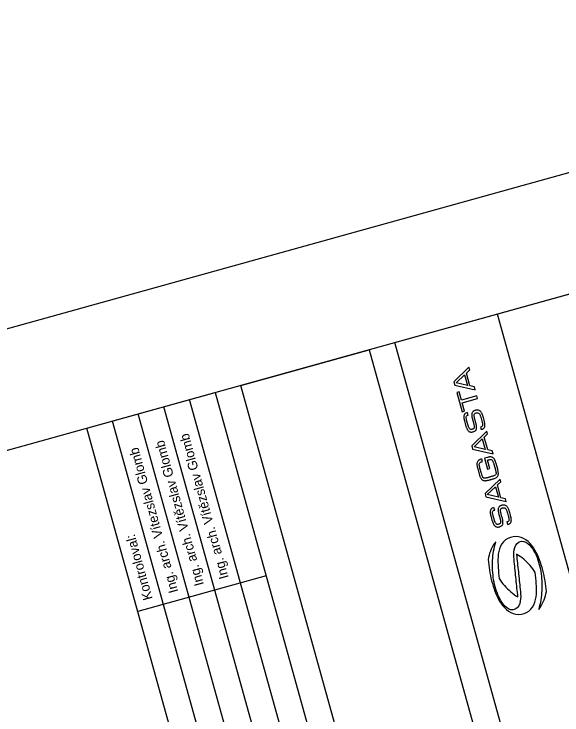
# Model space of a CAD drawing. Extents: x -821172 to -820632, y -1070921 to -1069931.
# Drawn here: x -820991 to -820939.6, y -1069996.3 to -1069930.6 of the extents above; entities that cross this region are included whole.
import ezdxf

# ---------------------------------------------------------------- set-up
doc = ezdxf.new("R2010")
doc.units = 0
doc.layers.add('Popisove_pole', color=7, linetype='Continuous')
doc.layers.add('Ram', color=7, linetype='Continuous')

# ---------------------------------------------------------------- blocks, each defined once
blk = doc.blocks.new('sagasta-logo')
at = {"layer": 'Popisove_pole'}
for p, q in [((-4.235, 0.826), (-4.328, 0.783)), ((-4.267, 0.757), (-4.186, 0.794)), ((-4.14, 0.863), (-4.235, 0.826)), ((-4.186, 0.794), (-4.101, 0.825)), ((-4.043, 0.893), (-4.14, 0.863)), ((-4.101, 0.825), (-4.015, 0.85)), ((-3.943, 0.916), (-4.043, 0.893)), ((-4.015, 0.85), (-3.927, 0.869)), ((-3.843, 0.934), (-3.943, 0.916)), ((-3.927, 0.869), (-3.838, 0.884)), ((-3.742, 0.949), (-3.843, 0.934)), ((-3.838, 0.884), (-3.749, 0.895)), ((-3.749, 0.895), (-3.659, 0.903)), ((-3.641, 0.96), (-3.742, 0.949)), ((-3.659, 0.903), (-3.569, 0.907)), ((-3.539, 0.968), (-3.641, 0.96)), ((-3.569, 0.907), (-3.479, 0.908)), ((-3.437, 0.972), (-3.539, 0.968)), ((-3.479, 0.908), (-3.389, 0.906)), ((-3.335, 0.975), (-3.437, 0.972)), ((-3.389, 0.906), (-3.3, 0.901)), ((-3.233, 0.976), (-3.335, 0.975)), ((-3.3, 0.901), (-3.21, 0.892)), ((-3.131, 0.975), (-3.233, 0.976)), ((-3.21, 0.892), (-3.121, 0.881)), ((-3.03, 0.97), (-3.131, 0.975)), ((-3.121, 0.881), (-3.032, 0.867)), ((-3.032, 0.867), (-2.944, 0.85)), ((-2.928, 0.962), (-3.03, 0.97)), ((-2.944, 0.85), (-2.855, 0.832)), ((-2.827, 0.951), (-2.928, 0.962)), ((-2.855, 0.832), (-2.768, 0.81)), ((-2.726, 0.938), (-2.827, 0.951)), ((-2.768, 0.81), (-2.681, 0.787)), ((-2.625, 0.922), (-2.726, 0.938)), ((-2.524, 0.907), (-2.625, 0.922)), ((-2.423, 0.891), (-2.524, 0.907)), ((-2.35, 0.855), (-2.423, 0.891)), ((-2.28, 0.814), (-2.35, 0.855)), ((-2.211, 0.77), (-2.28, 0.814)), ((-4.572, 0.602), (-4.634, 0.521)), ((-4.497, 0.67), (-4.572, 0.602)), ((-4.415, 0.731), (-4.497, 0.67)), ((-4.493, 0.493), (-4.465, 0.578)), ((-4.465, 0.578), (-4.412, 0.65)), ((-4.328, 0.783), (-4.415, 0.731)), ((-4.412, 0.65), (-4.343, 0.708)), ((-4.343, 0.708), (-4.267, 0.757)), ((-3.532, 0.564), (-3.606, 0.526)), ((-3.457, 0.599), (-3.532, 0.564)), ((-3.38, 0.629), (-3.457, 0.599)), ((-3.302, 0.655), (-3.38, 0.629)), ((-3.222, 0.677), (-3.302, 0.655)), ((-3.121, 0.662), (-3.222, 0.677)), ((-3.02, 0.646), (-3.121, 0.662)), ((-2.92, 0.627), (-3.02, 0.646)), ((-2.82, 0.606), (-2.92, 0.627)), ((-2.721, 0.584), (-2.82, 0.606)), ((-2.622, 0.559), (-2.721, 0.584)), ((-2.681, 0.787), (-2.595, 0.762)), ((-2.523, 0.533), (-2.622, 0.559)), ((-2.595, 0.762), (-2.509, 0.735)), ((-2.426, 0.503), (-2.523, 0.533)), ((-2.509, 0.735), (-2.424, 0.706)), ((-2.424, 0.706), (-2.339, 0.675)), ((-2.339, 0.675), (-2.257, 0.639)), ((-2.257, 0.639), (-2.174, 0.604)), ((-2.145, 0.722), (-2.211, 0.77)), ((-2.174, 0.604), (-2.093, 0.565)), ((-2.081, 0.671), (-2.145, 0.722)), ((-2.093, 0.565), (-2.013, 0.524)), ((-2.019, 0.617), (-2.081, 0.671)), ((-1.961, 0.56), (-2.019, 0.617)), ((-1.906, 0.5), (-1.961, 0.56)), ((-4.717, 0.335), (-4.736, 0.235)), ((-4.684, 0.432), (-4.717, 0.335)), ((-4.634, 0.521), (-4.684, 0.432)), ((-4.493, 0.403), (-4.493, 0.493)), ((-4.46, 0.319), (-4.493, 0.403)), ((-4.404, 0.248), (-4.46, 0.319)), ((-3.951, 0.298), (-4.014, 0.244)), ((-3.885, 0.348), (-3.951, 0.298)), ((-3.817, 0.396), (-3.885, 0.348)), ((-3.748, 0.442), (-3.817, 0.396)), ((-3.678, 0.485), (-3.748, 0.442)), ((-3.606, 0.526), (-3.678, 0.485)), ((-2.331, 0.466), (-2.426, 0.503)), ((-2.239, 0.422), (-2.331, 0.466)), ((-2.152, 0.369), (-2.239, 0.422)), ((-2.072, 0.306), (-2.152, 0.369)), ((-1.999, 0.234), (-2.072, 0.306)), ((-2.013, 0.524), (-1.935, 0.48)), ((-1.935, 0.48), (-1.857, 0.434)), ((-1.857, 0.434), (-1.906, 0.5)), ((-4.736, 0.235), (-4.741, 0.133)), ((-4.741, 0.133), (-4.727, 0.032)), ((-4.727, 0.032), (-4.699, -0.066)), ((-4.336, 0.19), (-4.404, 0.248)), ((-4.258, 0.144), (-4.336, 0.19)), ((-4.176, 0.108), (-4.258, 0.144)), ((-4.09, 0.082), (-4.176, 0.108)), ((-4.002, 0.063), (-4.09, 0.082)), ((-4.014, 0.244), (-4.073, 0.186)), ((-4.073, 0.186), (-3.991, 0.172)), ((-3.913, 0.046), (-4.002, 0.063)), ((-3.991, 0.172), (-3.91, 0.158)), ((-3.825, 0.03), (-3.913, 0.046)), ((-3.91, 0.158), (-3.828, 0.144)), ((-3.828, 0.144), (-3.747, 0.131)), ((-3.743, 0.016), (-3.825, 0.03)), ((-3.747, 0.131), (-3.665, 0.117)), ((-3.662, 0.002), (-3.743, 0.016)), ((-3.665, 0.117), (-3.584, 0.103)), ((-3.58, -0.012), (-3.662, 0.002)), ((-3.584, 0.103), (-3.502, 0.089)), ((-3.502, 0.089), (-3.421, 0.075)), ((-3.421, 0.075), (-3.339, 0.062)), ((-3.339, 0.062), (-3.257, 0.048)), ((-3.257, 0.048), (-3.176, 0.034)), ((-3.176, 0.034), (-3.094, 0.02)), ((-3.094, 0.02), (-3.013, 0.006)), ((-3.013, 0.006), (-2.931, -0.007)), ((-1.939, 0.152), (-1.999, 0.234)), ((-1.894, 0.061), (-1.939, 0.152)), ((-1.866, -0.037), (-1.894, 0.061)), ((-4.699, -0.066), (-4.654, -0.157)), ((-4.654, -0.157), (-4.594, -0.24)), ((-4.594, -0.24), (-4.521, -0.311)), ((-3.499, -0.025), (-3.58, -0.012)), ((-3.417, -0.039), (-3.499, -0.025)), ((-3.336, -0.053), (-3.417, -0.039)), ((-3.254, -0.067), (-3.336, -0.053)), ((-3.173, -0.081), (-3.254, -0.067)), ((-3.091, -0.094), (-3.173, -0.081)), ((-3.01, -0.108), (-3.091, -0.094)), ((-2.928, -0.122), (-3.01, -0.108)), ((-2.931, -0.007), (-2.85, -0.021)), ((-2.846, -0.136), (-2.928, -0.122)), ((-2.85, -0.021), (-2.768, -0.035)), ((-2.765, -0.15), (-2.846, -0.136)), ((-2.768, -0.035), (-2.68, -0.051)), ((-2.683, -0.163), (-2.765, -0.15)), ((-2.602, -0.177), (-2.683, -0.163)), ((-2.68, -0.051), (-2.591, -0.068)), ((-2.642, -0.304), (-2.58, -0.25)), ((-2.52, -0.191), (-2.602, -0.177)), ((-2.591, -0.068), (-2.504, -0.087)), ((-2.58, -0.25), (-2.52, -0.191)), ((-2.504, -0.087), (-2.417, -0.114)), ((-2.417, -0.114), (-2.335, -0.149)), ((-2.335, -0.149), (-2.258, -0.195)), ((-2.258, -0.195), (-2.189, -0.253)), ((-2.189, -0.253), (-2.134, -0.324)), ((-1.876, -0.34), (-1.857, -0.24)), ((-1.852, -0.139), (-1.866, -0.037)), ((-1.857, -0.24), (-1.852, -0.139)), ((-4.659, -0.485), (-4.736, -0.439)), ((-4.736, -0.439), (-4.687, -0.505)), ((-4.687, -0.505), (-4.632, -0.565)), ((-4.58, -0.529), (-4.659, -0.485)), ((-4.521, -0.311), (-4.441, -0.374)), ((-4.441, -0.374), (-4.354, -0.428)), ((-4.354, -0.428), (-4.262, -0.471)), ((-4.262, -0.471), (-4.167, -0.508)), ((-4.167, -0.508), (-4.07, -0.538)), ((-2.987, -0.531), (-2.915, -0.49)), ((-2.915, -0.49), (-2.845, -0.447)), ((-2.845, -0.447), (-2.776, -0.401)), ((-2.776, -0.401), (-2.708, -0.354)), ((-2.708, -0.354), (-2.642, -0.304)), ((-2.134, -0.324), (-2.1, -0.408)), ((-2.1, -0.498), (-2.128, -0.583)), ((-2.1, -0.408), (-2.1, -0.498)), ((-2.021, -0.607), (-1.959, -0.526)), ((-1.959, -0.526), (-1.909, -0.437)), ((-1.909, -0.437), (-1.876, -0.34)), ((-4.632, -0.565), (-4.574, -0.622)), ((-4.5, -0.57), (-4.58, -0.529)), ((-4.574, -0.622), (-4.512, -0.676)), ((-4.512, -0.676), (-4.449, -0.727)), ((-4.419, -0.609), (-4.5, -0.57)), ((-4.449, -0.727), (-4.382, -0.775)), ((-4.336, -0.644), (-4.419, -0.609)), ((-4.382, -0.775), (-4.314, -0.819)), ((-4.254, -0.68), (-4.336, -0.644)), ((-4.169, -0.711), (-4.254, -0.68)), ((-4.084, -0.74), (-4.169, -0.711)), ((-3.998, -0.767), (-4.084, -0.74)), ((-4.07, -0.538), (-3.971, -0.564)), ((-3.912, -0.792), (-3.998, -0.767)), ((-3.971, -0.564), (-3.872, -0.589)), ((-3.872, -0.589), (-3.773, -0.611)), ((-3.773, -0.611), (-3.673, -0.632)), ((-3.673, -0.632), (-3.573, -0.651)), ((-3.573, -0.651), (-3.472, -0.667)), ((-3.472, -0.667), (-3.371, -0.682)), ((-3.371, -0.682), (-3.291, -0.661)), ((-3.291, -0.661), (-3.213, -0.635)), ((-3.213, -0.635), (-3.136, -0.604)), ((-3.136, -0.604), (-3.061, -0.569)), ((-3.061, -0.569), (-2.987, -0.531)), ((-2.326, -0.762), (-2.407, -0.8)), ((-2.358, -0.831), (-2.266, -0.788)), ((-2.25, -0.713), (-2.326, -0.762)), ((-2.266, -0.788), (-2.178, -0.736)), ((-2.181, -0.655), (-2.25, -0.713)), ((-2.128, -0.583), (-2.181, -0.655)), ((-2.178, -0.736), (-2.096, -0.675)), ((-2.096, -0.675), (-2.021, -0.607)), ((-4.314, -0.819), (-4.243, -0.861)), ((-4.243, -0.861), (-4.17, -0.896)), ((-4.17, -0.896), (-4.069, -0.912)), ((-4.069, -0.912), (-3.968, -0.928)), ((-3.968, -0.928), (-3.868, -0.943)), ((-3.825, -0.815), (-3.912, -0.792)), ((-3.868, -0.943), (-3.766, -0.956)), ((-3.738, -0.837), (-3.825, -0.815)), ((-3.766, -0.956), (-3.665, -0.967)), ((-3.65, -0.855), (-3.738, -0.837)), ((-3.665, -0.967), (-3.564, -0.976)), ((-3.561, -0.872), (-3.65, -0.855)), ((-3.564, -0.976), (-3.462, -0.98)), ((-3.472, -0.886), (-3.561, -0.872)), ((-3.383, -0.897), (-3.472, -0.886)), ((-3.462, -0.98), (-3.36, -0.982)), ((-3.294, -0.906), (-3.383, -0.897)), ((-3.36, -0.982), (-3.258, -0.981)), ((-3.204, -0.911), (-3.294, -0.906)), ((-3.258, -0.981), (-3.156, -0.978)), ((-3.114, -0.913), (-3.204, -0.911)), ((-3.156, -0.978), (-3.054, -0.973)), ((-3.024, -0.912), (-3.114, -0.913)), ((-3.054, -0.973), (-2.952, -0.966)), ((-2.934, -0.908), (-3.024, -0.912)), ((-2.952, -0.966), (-2.851, -0.955)), ((-2.844, -0.9), (-2.934, -0.908)), ((-2.851, -0.955), (-2.75, -0.94)), ((-2.755, -0.889), (-2.844, -0.9)), ((-2.666, -0.874), (-2.755, -0.889)), ((-2.75, -0.94), (-2.65, -0.922)), ((-2.579, -0.855), (-2.666, -0.874)), ((-2.65, -0.922), (-2.551, -0.898)), ((-2.492, -0.83), (-2.579, -0.855)), ((-2.551, -0.898), (-2.453, -0.868)), ((-2.407, -0.8), (-2.492, -0.83)), ((-2.453, -0.868), (-2.358, -0.831))]:
    blk.add_line(p, q, dxfattribs=at)
for points in [[(-0.604, -0.144), (-0.605, -0.121), (-0.607, -0.098), (-0.608, -0.09), (-0.613, -0.068), (-0.622, -0.048), (-0.625, -0.042), (-0.637, -0.023), (-0.654, -0.007), (-0.667, 0.003), (-0.686, 0.013), (-0.709, 0.023), (-0.724, 0.027), (-0.745, 0.032), (-0.767, 0.037), (-0.792, 0.04), (-0.796, 0.04), (-0.816, 0.042), (-0.837, 0.044), (-0.859, 0.045), (-0.883, 0.046), (-0.908, 0.046), (-1.02, 0.046), (-1.025, 0.046), (-1.051, 0.046), (-1.074, 0.046), (-1.095, 0.047), (-1.114, 0.048), (-1.136, 0.05), (-1.158, 0.052), (-1.178, 0.056), (-1.201, 0.062), (-1.224, 0.072), (-1.244, 0.091), (-1.253, 0.115), (-1.254, 0.129), (-1.255, 0.152), (-1.255, 0.165), (-1.251, 0.188), (-1.243, 0.211), (-1.226, 0.229), (-1.205, 0.241), (-1.193, 0.246), (-1.174, 0.252), (-1.151, 0.256), (-1.125, 0.26), (-1.108, 0.262), (-1.088, 0.263), (-1.067, 0.264), (-1.043, 0.265), (-1.019, 0.266), (-0.993, 0.266), (-0.911, 0.266), (-0.897, 0.266), (-0.872, 0.266), (-0.849, 0.265), (-0.829, 0.264), (-0.81, 0.263), (-0.785, 0.26), (-0.763, 0.256), (-0.745, 0.25), (-0.725, 0.237), (-0.713, 0.22), (-0.707, 0.204), (-0.704, 0.182), (-0.703, 0.154), (-0.604, 0.154), (-0.604, 0.179), (-0.606, 0.202), (-0.609, 0.222), (-0.61, 0.23), (-0.618, 0.252), (-0.628, 0.271), (-0.633, 0.278), (-0.647, 0.294), (-0.665, 0.309), (-0.68, 0.317), (-0.7, 0.326), (-0.722, 0.334), (-0.736, 0.338), (-0.757, 0.342), (-0.779, 0.346), (-0.803, 0.349), (-0.82, 0.35), (-0.842, 0.352), (-0.864, 0.353), (-0.887, 0.353), (-0.911, 0.354), (-0.993, 0.354), (-1.014, 0.354), (-1.038, 0.353), (-1.061, 0.352), (-1.083, 0.351), (-1.103, 0.35), (-1.123, 0.348), (-1.134, 0.347), (-1.158, 0.344), (-1.18, 0.34), (-1.201, 0.336), (-1.22, 0.33), (-1.226, 0.329), (-1.249, 0.321), (-1.269, 0.312), (-1.286, 0.302), (-1.298, 0.294), (-1.314, 0.278), (-1.328, 0.262), (-1.333, 0.254), (-1.342, 0.234), (-1.349, 0.212), (-1.351, 0.199), (-1.354, 0.176), (-1.354, 0.152), (-1.354, 0.141), (-1.353, 0.118), (-1.351, 0.096), (-1.35, 0.09), (-1.344, 0.068), (-1.335, 0.048), (-1.331, 0.041), (-1.318, 0.024), (-1.3, 0.008), (-1.283, -0.002), (-1.263, -0.012), (-1.24, -0.02), (-1.237, -0.021), (-1.218, -0.026), (-1.197, -0.03), (-1.174, -0.033), (-1.149, -0.036), (-1.134, -0.038), (-1.114, -0.04), (-1.092, -0.041), (-1.069, -0.042), (-1.045, -0.042), (-1.02, -0.042), (-0.908, -0.042), (-0.885, -0.042), (-0.861, -0.043), (-0.838, -0.044), (-0.818, -0.046), (-0.8, -0.048), (-0.776, -0.053), (-0.754, -0.059), (-0.737, -0.067), (-0.72, -0.082), (-0.709, -0.101), (-0.707, -0.11), (-0.704, -0.131), (-0.703, -0.156), (-0.703, -0.17), (-0.706, -0.193), (-0.715, -0.217), (-0.73, -0.236), (-0.749, -0.25), (-0.756, -0.253), (-0.775, -0.26), (-0.797, -0.266), (-0.822, -0.271), (-0.826, -0.272), (-0.845, -0.274), (-0.866, -0.276), (-0.888, -0.277), (-0.912, -0.278), (-0.938, -0.278), (-1.047, -0.278), (-1.063, -0.278), (-1.088, -0.278), (-1.11, -0.277), (-1.131, -0.276), (-1.149, -0.275), (-1.172, -0.273), (-1.194, -0.268), (-1.213, -0.262), (-1.232, -0.249), (-1.245, -0.231), (-1.25, -0.215), (-1.254, -0.193), (-1.255, -0.165), (-1.354, -0.165), (-1.353, -0.191), (-1.352, -0.214), (-1.349, -0.233), (-1.347, -0.241), (-1.34, -0.263), (-1.329, -0.282), (-1.325, -0.288), (-1.311, -0.305), (-1.293, -0.32), (-1.279, -0.329), (-1.258, -0.338), (-1.236, -0.346), (-1.223, -0.35), (-1.202, -0.354), (-1.179, -0.358), (-1.155, -0.361), (-1.138, -0.362), (-1.118, -0.364), (-1.095, -0.365), (-1.072, -0.365), (-1.047, -0.366), (-0.938, -0.366), (-0.928, -0.366), (-0.904, -0.365), (-0.881, -0.364), (-0.858, -0.363), (-0.838, -0.362), (-0.818, -0.36), (-0.792, -0.355), (-0.77, -0.351), (-0.749, -0.346), (-0.727, -0.339), (-0.705, -0.331), (-0.685, -0.321), (-0.668, -0.309), (-0.658, -0.301), (-0.642, -0.285), (-0.629, -0.268), (-0.624, -0.259), (-0.615, -0.238), (-0.609, -0.216), (-0.607, -0.202), (-0.604, -0.18), (-0.604, -0.156), (-0.604, -0.144)], [(-0.012, 0.339), (-0.139, 0.339), (-0.515, -0.351), (-0.406, -0.351), (-0.322, -0.197), (0.179, -0.197), (0.263, -0.351), (0.363, -0.351), (-0.012, 0.339)], [(-0.071, 0.266), (0.136, -0.109), (-0.279, -0.109), (-0.071, 0.266)], [(0.556, 0.205), (0.565, 0.223), (0.579, 0.238), (0.599, 0.249), (0.612, 0.254), (0.633, 0.259), (0.658, 0.262), (0.659, 0.262), (0.678, 0.263), (0.7, 0.264), (0.723, 0.265), (0.748, 0.265), (0.967, 0.265), (0.981, 0.265), (1.005, 0.264), (1.028, 0.263), (1.049, 0.262), (1.067, 0.26), (1.069, 0.26), (1.093, 0.256), (1.114, 0.25), (1.132, 0.242), (1.14, 0.236), (1.155, 0.22), (1.165, 0.199), (1.169, 0.184), (1.173, 0.164), (1.175, 0.139), (1.175, 0.111), (1.274, 0.111), (1.274, 0.125), (1.274, 0.149), (1.272, 0.172), (1.269, 0.191), (1.266, 0.208), (1.259, 0.23), (1.25, 0.25), (1.243, 0.263), (1.23, 0.28), (1.214, 0.296), (1.197, 0.308), (1.178, 0.319), (1.156, 0.328), (1.142, 0.333), (1.121, 0.338), (1.099, 0.343), (1.075, 0.346), (1.058, 0.349), (1.036, 0.35), (1.014, 0.352), (0.991, 0.353), (0.967, 0.353), (0.748, 0.353), (0.729, 0.353), (0.704, 0.352), (0.681, 0.351), (0.66, 0.349), (0.639, 0.346), (0.621, 0.343), (0.617, 0.343), (0.593, 0.337), (0.572, 0.33), (0.552, 0.323), (0.534, 0.313), (0.527, 0.309), (0.508, 0.296), (0.493, 0.28), (0.48, 0.263), (0.476, 0.257), (0.466, 0.237), (0.458, 0.216), (0.453, 0.192), (0.449, 0.173), (0.446, 0.151), (0.444, 0.128), (0.443, 0.103), (0.442, 0.087), (0.442, 0.065), (0.441, 0.042), (0.441, 0.019), (0.441, -0.006), (0.441, -0.025), (0.441, -0.049), (0.442, -0.072), (0.442, -0.094), (0.443, -0.115), (0.444, -0.139), (0.446, -0.162), (0.449, -0.184), (0.453, -0.205), (0.454, -0.213), (0.461, -0.235), (0.469, -0.256), (0.48, -0.275), (0.484, -0.282), (0.498, -0.298), (0.514, -0.313), (0.537, -0.328), (0.554, -0.336), (0.574, -0.344), (0.596, -0.35), (0.62, -0.355), (0.635, -0.358), (0.655, -0.36), (0.676, -0.362), (0.699, -0.364), (0.723, -0.365), (0.748, -0.365), (0.967, -0.365), (0.989, -0.365), (1.013, -0.364), (1.035, -0.363), (1.056, -0.361), (1.076, -0.359), (1.093, -0.356), (1.116, -0.352), (1.137, -0.346), (1.156, -0.34), (1.178, -0.33), (1.197, -0.319), (1.214, -0.306), (1.225, -0.295), (1.239, -0.278), (1.25, -0.258), (1.258, -0.24), (1.265, -0.219), (1.269, -0.195), (1.27, -0.187), (1.273, -0.166), (1.274, -0.142), (1.274, -0.118), (1.274, 0.003), (0.849, 0.003), (0.849, -0.085), (1.175, -0.085), (1.175, -0.118), (1.175, -0.133), (1.174, -0.157), (1.172, -0.178), (1.169, -0.2), (1.162, -0.22), (1.156, -0.231), (1.141, -0.248), (1.127, -0.257), (1.105, -0.265), (1.094, -0.268), (1.073, -0.272), (1.049, -0.274), (1.036, -0.275), (1.015, -0.276), (0.992, -0.277), (0.967, -0.277), (0.748, -0.277), (0.746, -0.277), (0.72, -0.277), (0.697, -0.276), (0.676, -0.275), (0.657, -0.274), (0.641, -0.272), (0.618, -0.267), (0.6, -0.261), (0.58, -0.25), (0.564, -0.234), (0.554, -0.212), (0.548, -0.187), (0.545, -0.165), (0.542, -0.142), (0.541, -0.117), (0.541, -0.102), (0.541, -0.081), (0.541, -0.058), (0.54, -0.033), (0.54, -0.006), (0.54, 0.018), (0.541, 0.043), (0.541, 0.066), (0.541, 0.087), (0.541, 0.105), (0.541, 0.108), (0.542, 0.133), (0.545, 0.156), (0.548, 0.179), (0.556, 0.205)], [(1.854, 0.339), (1.727, 0.339), (1.351, -0.351), (1.459, -0.351), (1.544, -0.197), (2.044, -0.197), (2.129, -0.351), (2.229, -0.351), (1.854, 0.339)], [(1.795, 0.266), (2.002, -0.109), (1.586, -0.109), (1.795, 0.266)], [(2.458, 0.089), (2.455, 0.094), (2.447, 0.115), (2.446, 0.129), (2.445, 0.152), (2.445, 0.165), (2.449, 0.188), (2.457, 0.211), (2.474, 0.229), (2.495, 0.241), (2.507, 0.246), (2.526, 0.252), (2.549, 0.256), (2.575, 0.26), (2.592, 0.262), (2.612, 0.263), (2.634, 0.264), (2.657, 0.265), (2.681, 0.266), (2.707, 0.266), (2.789, 0.266), (2.803, 0.266), (2.828, 0.266), (2.851, 0.265), (2.871, 0.264), (2.89, 0.263), (2.915, 0.26), (2.937, 0.256), (2.955, 0.25), (2.975, 0.237), (2.988, 0.22), (2.993, 0.204), (2.996, 0.182), (2.997, 0.154), (3.097, 0.154), (3.096, 0.179), (3.094, 0.202), (3.091, 0.222), (3.09, 0.23), (3.082, 0.252), (3.072, 0.271), (3.067, 0.278), (3.053, 0.294), (3.035, 0.309), (3.02, 0.317), (3.001, 0.326), (2.978, 0.334), (2.964, 0.338), (2.943, 0.342), (2.921, 0.346), (2.897, 0.349), (2.88, 0.35), (2.859, 0.352), (2.837, 0.353), (2.813, 0.353), (2.789, 0.354), (2.707, 0.354), (2.686, 0.354), (2.662, 0.353), (2.639, 0.352), (2.617, 0.351), (2.597, 0.35), (2.577, 0.348), (2.566, 0.347), (2.542, 0.344), (2.52, 0.34), (2.499, 0.336), (2.48, 0.33), (2.474, 0.329), (2.452, 0.321), (2.431, 0.312), (2.414, 0.302), (2.402, 0.294), (2.386, 0.278), (2.372, 0.262), (2.367, 0.254), (2.358, 0.234), (2.351, 0.212), (2.349, 0.199), (2.346, 0.176), (2.346, 0.152), (2.346, 0.141), (2.347, 0.118), (2.349, 0.096), (2.35, 0.09), (2.356, 0.068), (2.365, 0.048), (2.369, 0.041), (2.382, 0.024), (2.4, 0.008), (2.417, -0.002), (2.437, -0.012), (2.46, -0.02), (2.463, -0.021), (2.482, -0.026), (2.503, -0.03), (2.526, -0.033), (2.551, -0.036), (2.566, -0.038), (2.587, -0.04), (2.608, -0.041), (2.631, -0.042), (2.655, -0.042), (2.68, -0.042), (2.792, -0.042), (2.815, -0.042), (2.84, -0.043), (2.862, -0.044), (2.882, -0.046), (2.9, -0.048), (2.925, -0.053), (2.946, -0.059), (2.963, -0.067), (2.98, -0.082), (2.991, -0.101), (2.993, -0.11), (2.996, -0.131), (2.997, -0.156), (2.997, -0.17), (2.994, -0.193), (2.985, -0.217), (2.97, -0.236), (2.951, -0.25), (2.944, -0.253), (2.926, -0.26), (2.904, -0.266), (2.878, -0.271), (2.874, -0.272), (2.855, -0.274), (2.834, -0.276), (2.812, -0.277), (2.788, -0.278), (2.762, -0.278), (2.653, -0.278), (2.637, -0.278), (2.612, -0.278), (2.59, -0.277), (2.569, -0.276), (2.551, -0.275), (2.528, -0.273), (2.506, -0.268), (2.488, -0.262), (2.468, -0.249), (2.455, -0.231), (2.45, -0.215), (2.446, -0.193), (2.445, -0.165), (2.346, -0.165), (2.347, -0.191), (2.348, -0.214), (2.351, -0.233), (2.353, -0.241), (2.36, -0.263), (2.371, -0.282), (2.375, -0.288), (2.389, -0.305), (2.407, -0.32), (2.422, -0.329), (2.442, -0.338), (2.464, -0.346), (2.478, -0.35), (2.498, -0.354), (2.521, -0.358), (2.545, -0.361), (2.562, -0.362), (2.583, -0.364), (2.605, -0.365), (2.628, -0.365), (2.653, -0.366), (2.762, -0.366), (2.772, -0.366), (2.797, -0.365), (2.82, -0.364), (2.842, -0.363), (2.862, -0.362), (2.882, -0.36), (2.884, -0.359), (2.908, -0.355), (2.93, -0.351), (2.951, -0.346), (2.974, -0.339), (2.995, -0.331), (3.015, -0.321), (3.032, -0.309), (3.043, -0.301), (3.058, -0.285), (3.071, -0.268), (3.076, -0.259), (3.085, -0.238), (3.091, -0.216), (3.093, -0.202), (3.096, -0.18), (3.097, -0.156), (3.096, -0.144), (3.095, -0.121), (3.093, -0.098), (3.092, -0.09), (3.087, -0.068), (3.078, -0.048), (3.075, -0.042), (3.063, -0.023), (3.046, -0.007), (3.033, 0.003), (3.014, 0.013), (2.991, 0.023), (2.976, 0.027), (2.955, 0.032), (2.933, 0.037), (2.908, 0.04), (2.904, 0.04), (2.884, 0.042), (2.863, 0.044), (2.841, 0.045), (2.817, 0.046), (2.792, 0.046), (2.68, 0.046), (2.675, 0.046), (2.649, 0.046), (2.626, 0.046), (2.605, 0.047), (2.587, 0.048), (2.564, 0.05), (2.542, 0.052), (2.522, 0.056), (2.499, 0.062), (2.476, 0.072), (2.458, 0.089)], [(3.931, 0.339), (3.18, 0.339), (3.18, 0.251), (3.506, 0.251), (3.506, -0.351), (3.605, -0.351), (3.605, 0.251), (3.931, 0.251), (3.931, 0.339)], [(4.347, 0.339), (4.22, 0.339), (3.844, -0.351), (3.952, -0.351), (4.037, -0.197), (4.537, -0.197), (4.622, -0.351), (4.722, -0.351), (4.347, 0.339)], [(4.288, 0.266), (4.495, -0.109), (4.079, -0.109), (4.288, 0.266)]]:
    blk.add_lwpolyline(points, dxfattribs=at)

msp = doc.modelspace()

# ---------------------------------------------------------------- linework, layer by layer
at = {"layer": 'Popisove_pole'}
for p, q in [((-820922.874, -1070040.602), (-820945.63, -1069958.705)), ((-820951.779, -1070048.634), (-820974.535, -1069966.737)), ((-820954.187, -1070049.303), (-820976.944, -1069967.406)), ((-820956.596, -1070049.972), (-820979.353, -1069968.075)), ((-820959.005, -1070050.642), (-820981.761, -1069968.745)), ((-820967.348, -1069983.266), (-820979.391, -1069986.612))]:
    msp.add_line(p, q, dxfattribs=at)
for points in [[(-820992.727, -1070060.012), (-821015.484, -1069978.115), (-820890.229, -1069943.311), (-820867.473, -1070025.208)], [(-820932.509, -1070043.279), (-820955.265, -1069961.382), (-820931.178, -1069954.689), (-820908.421, -1070036.586)], [(-820946.961, -1070047.295), (-820969.718, -1069965.398), (-820957.674, -1069962.052), (-820934.917, -1070043.949)], [(-820961.414, -1070051.311), (-820984.17, -1069969.414), (-820972.127, -1069966.067), (-820949.37, -1070047.965)]]:
    msp.add_lwpolyline(points, close=True, dxfattribs=at)
at = {"layer": 'Ram'}
msp.add_lwpolyline([(-821000.428, -1070071.476), (-821028.539, -1069970.309), (-820885.46, -1069930.552), (-820857.349, -1070031.719)], dxfattribs=at)

# ---------------------------------------------------------------- block references
at = {"layer": 'Popisove_pole', "xscale": 2.499999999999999, "yscale": 2.5, "rotation": 105.52891348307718}
msp.add_blockref('sagasta-logo', (-820945.983, -1069975.306), dxfattribs=at)

# ---------------------------------------------------------------- texts
at = {"layer": 'Popisove_pole'}
for s, p in [('Ing. arch. Vítězslav Glomb', (-820970.849, -1069983.436)), ('Ing. arch. Vítězslav Glomb', (-820973.169, -1069984.081)), ('Ing. arch. Vítezslav Glomb', (-820975.577, -1069984.75)), ('Kontroloval:', (-820977.986, -1069985.419))]:
    msp.add_text(s, height=0.9, rotation=105.52891, dxfattribs=at).set_placement(p)

doc.saveas('drawing.dxf')
